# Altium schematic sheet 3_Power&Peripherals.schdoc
size 309 x 223 mm; Symbol: Artery_A4; Device: Artery_A4; Company: Artery Technology; Drawed: SD; Version: 1.1; Page Size: A4; @Project Name: p_AT-START-F437; @Page Count: 5; @Update Date: 2023-04-14 17:11:57; @Create Date: 2022-12-01; @Schematic Name: AT-START-F437 V1.1; @Page No: 3; @Page Name: Power&Peripherals
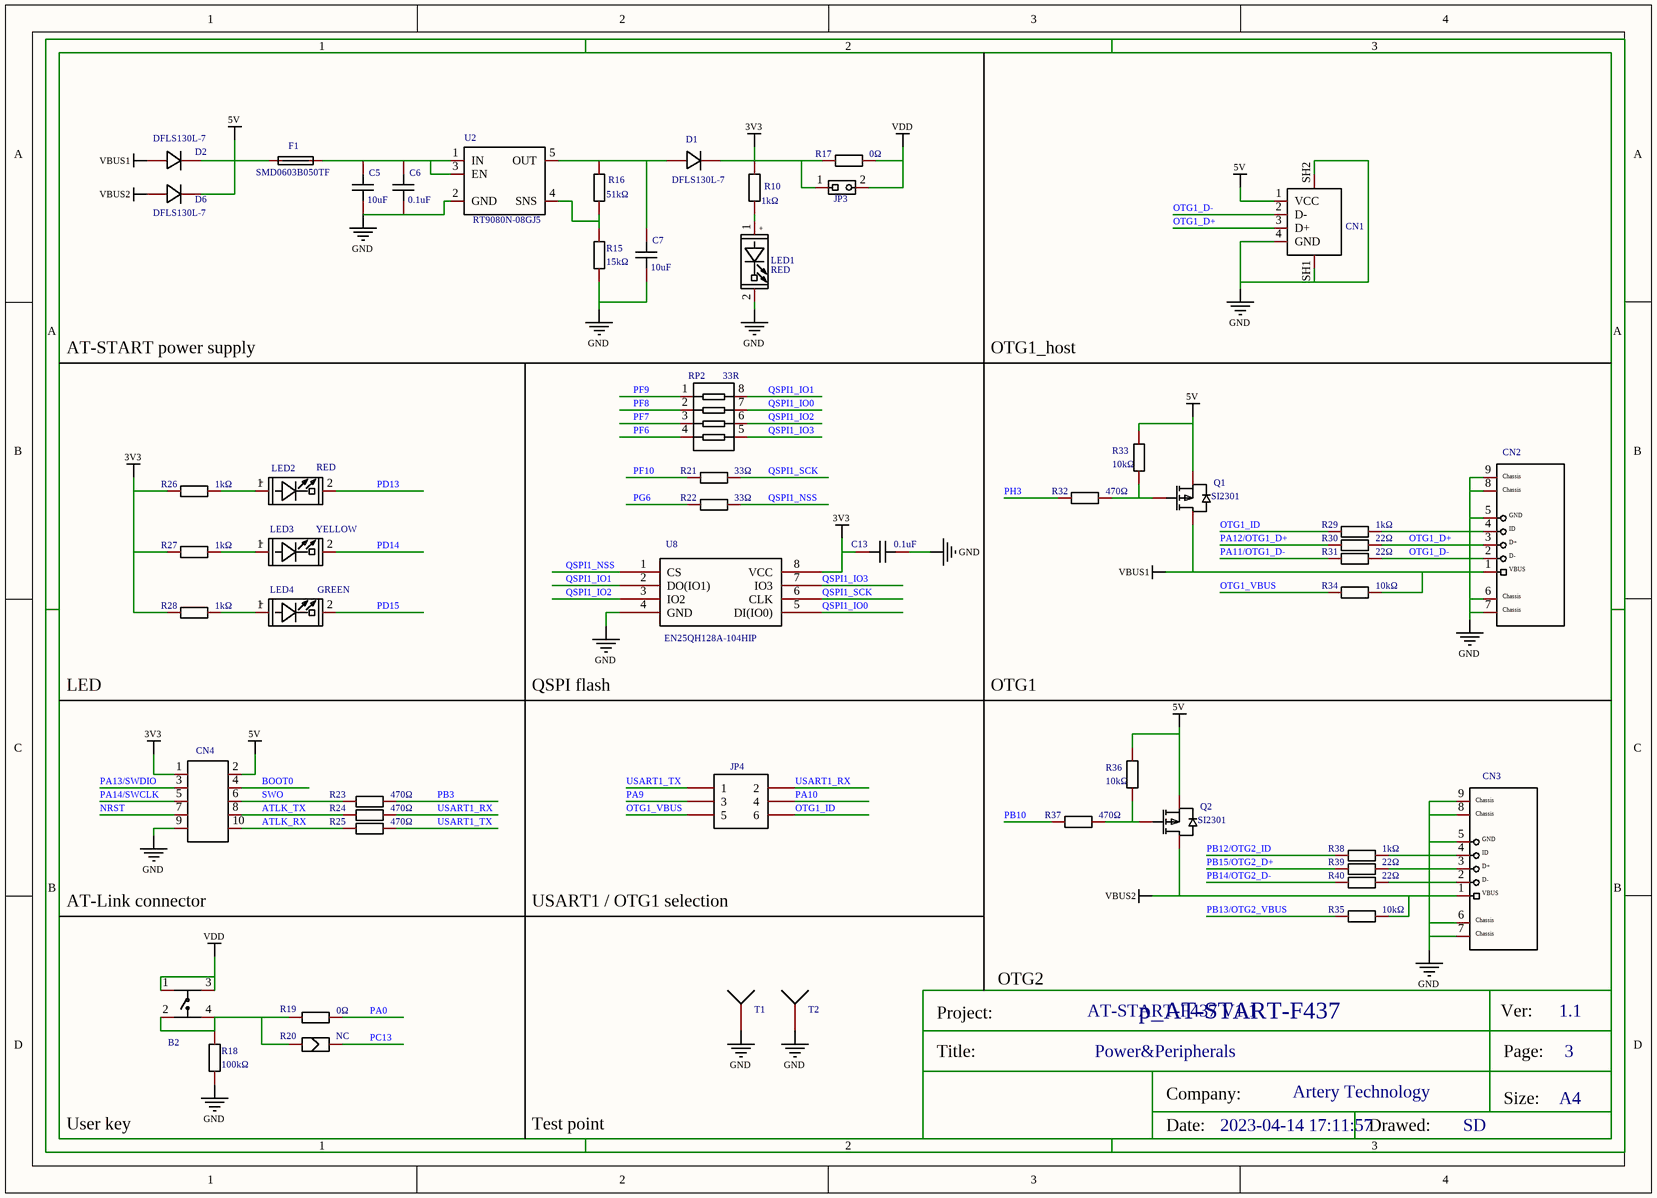
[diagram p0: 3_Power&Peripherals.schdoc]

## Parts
B2  贴片按键6*6*5 红色  [SW-SMD_4P-L6.0-W6.0-P4.50-LS9.0]  (value not drawn)
C5  10uF  [0603_C-M]
C6  0.1uF  [0603_C-M]
C7  10uF  [0603_C-M]
C13  0.1uF  [0603_C-M]
CN1  JTJ-USB-AF-08  [USB-A-TH__USB-AF-90]  (value not drawn)
CN2  USB_micro B  [USB_MIC_DIP]  (value not drawn)
CN3  USB_micro B  [USB_MIC_DIP]  (value not drawn)
CN4  CON10A_0  [HDR2X5]  (value not drawn)
D1  DFLS130L-7  [POWERDI-123_L2.8-W1.8-LS3.7-RD]
D2  DFLS130L-7  [POWERDI-123_L2.8-W1.8-LS3.7-RD]
D6  DFLS130L-7  [POWERDI-123_L2.8-W1.8-LS3.7-RD]
F1  SMD0603B050TF  [R0603]
JP3  Jumper 1x2P  [HEADER 1X2]  (value not drawn)
JP4  Header 3X2  [HDR2X3]  (value not drawn)
LED1  RED  [LED0603]
LED2  RED  [LED0603]
LED3  YELLOW  [LED0603]
LED4  GREEN  [LED0603]
Q1  SI2301  [SOT-23-3_L2.9-W1.3-P1.90-LS2.4-BR]
Q2  SI2301  [SOT-23-3_L2.9-W1.3-P1.90-LS2.4-BR]
R10  1kΩ  [R0603]
R15  15kΩ  [R0603]
R16  51kΩ  [R0603]
R17  0Ω  [R0603]
R18  100kΩ  [R0603]
R19  0Ω  [R0603]
R20  NC  [SB-PAD]
R21  33Ω  [R0603]
R22  33Ω  [R0603]
R23  470Ω  [R0603]
R24  470Ω  [R0603]
R25  470Ω  [R0603]
R26  1kΩ  [R0603]
R27  1kΩ  [R0603]
R28  1kΩ  [R0603]
R29  1kΩ  [R0603]
R30  22Ω  [R0603]
R31  22Ω  [R0603]
R32  470Ω  [R0603]
R33  10kΩ  [R0603]
R34  10kΩ  [R0603]
R35  10kΩ  [R0603]
R36  10kΩ  [R0603]
R37  470Ω  [R0603]
R38  1kΩ  [R0603]
R39  22Ω  [R0603]
R40  22Ω  [R0603]
RP2  33R  [0603*4,8P4R]
T1  TESTPOINT TP-5006  [TESTHOOK]  (value not drawn)
T2  TESTPOINT TP-5006  [TESTHOOK]  (value not drawn)
U2  RT9080N-08GJ5  [SOT-23-5]
U8  EN25QH128A-104HIP  [SOIC-8_208MIL]

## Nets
3V3: C13.1 CN4.1 D1.1 JP3.1 R10.1 R17.1 R26.1 R27.1 R28.1 U8.8(VCC)
5V: CN1.1(VCC) CN4.2 D2.1 D6.1 F1.1 Q1.2(S) Q2.2(S) R33.2 R36.2
GND: C5.2 C6.2 C7.2 C13.2 CN1.4(GND) CN1.SH1 CN1.SH2 CN2.5(GND) CN2.6 CN2.7 CN2.8 CN2.9 CN3.5(GND) CN3.6 CN3.7 CN3.8 CN3.9 CN4.9 LED1.2(CATHODE) R15.2 R18.1 T1.1 T2.1 U2.2(GND) U8.4(GND)
VBUS1: CN2.1(VBUS) D2.2 Q1.3(D) R34.2
VBUS2: CN3.1(VBUS) D6.2 Q2.3(D) R35.2
VDD: B2.1 B2.3 JP3.2 R17.2
ATLK_RX: CN4.10 R25.1
ATLK_TX: CN4.8 R24.1
BOOT0: CN4.4
NRST: CN4.7
OTG1_D+: CN1.3(D+) CN2.3(D+) R30.2
OTG1_D-: CN1.2(D-) CN2.2(D-) R31.2
OTG1_ID: JP4.6 R29.1
OTG1_VBUS: JP4.5 R34.1
PA0: R19.2
PA9: JP4.3
PA10: JP4.4
PA11/OTG1_D-: R31.1
PA12/OTG1_D+: R30.1
PA13/SWDIO: CN4.3
PA14/SWCLK: CN4.5
PB3: R23.2
PB10: R37.1
PB12/OTG2_ID: R38.1
PB13/OTG2_VBUS: R35.1
PB14/OTG2_D-: R40.1
PB15/OTG2_D+: R39.1
PC13: R20.2
PD13: LED2.2(CATHODE)
PD14: LED3.2(CATHODE)
PD15: LED4.2(CATHODE)
PF6: RP2.4
PF7: RP2.3
PF8: RP2.2
PF9: RP2.1
PF10: R21.1
PG6: R22.1
PH3: R32.1
QSPI1_IO0: RP2.7 U8.5(DI(IO0))
QSPI1_IO1: RP2.8 U8.2(DO(IO1))
QSPI1_IO2: RP2.6 U8.3(IO2)
QSPI1_IO3: RP2.5 U8.7(IO3)
QSPI1_NSS: R22.2 U8.1(CS)
QSPI1_SCK: R21.2 U8.6(CLK)
SWO: CN4.6 R23.1
USART1_RX: JP4.2 R24.2
USART1_TX: JP4.1 R25.2
NetB2_2: B2.2 B2.4 R18.2 R19.1 R20.1
NetC5_1: C5.1 C6.1 F1.2 U2.1(IN) U2.3(EN)
NetC7_1: C7.1 D1.2 R16.2 U2.5(OUT)
NetCN2_4: CN2.4(ID) R29.2
NetCN3_2: CN3.2(D-) R40.2
NetCN3_3: CN3.3(D+) R39.2
NetCN3_4: CN3.4(ID) R38.2
NetLED1_1: LED1.1(ANODE) R10.2
NetLED2_1: LED2.1(ANODE) R26.2
NetLED3_1: LED3.1(ANODE) R27.2
NetLED4_1: LED4.1(ANODE) R28.2
NetQ1_1: Q1.1(G) R32.2 R33.1
NetQ2_1: Q2.1(G) R36.1 R37.2
NetR15_1: R15.1 R16.1 U2.4(SNS)

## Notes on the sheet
- AT-START power supply
- OTG1_host
- LED
- QSPI flash
- OTG1
- AT-Link connector
- USART1 / OTG1 selection
- OTG2
- User key
- Test point

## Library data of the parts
B2 = K2-1102SP-C3SC-04: Manufacturer: Korean Hroparts Elec; Symbol: 贴片按键6*6*5 黑色; Paste Type: expand; Convert to PCB: yes
C5 C7 = 10uF: Convert to PCB: yes
C6 C13 = 0.1uF: Convert to PCB: yes
CN1 = JTJ-USB-AF-08: Paste Type: expand; Convert to PCB: yes
CN2 CN3 = USB_micro B: Convert to PCB: yes
CN4 = CON10A_0: Convert to PCB: yes
D1 D2 D6 = DFLS130L-7: Manufacturer: Diodes Incorporated; Paste Type: expand; Convert to PCB: yes
F1 = SMD0603B035TF: Manufacturer: Brightking Elec (TAIWAN); Paste Type: expand; Convert to PCB: yes
JP3 = Jumper 1x2P: Convert to PCB: yes
JP4 = Header 3X2: Convert to PCB: yes
LED1 LED2 = RED: Convert to PCB: yes
LED3 = YELLOW: Convert to PCB: yes
LED4 = GREEN: Convert to PCB: yes
Q1 Q2 = 2301: Manufacturer: FM; Paste Type: recommend; Convert to PCB: yes
R10 R26-R29 R38 = 0603WAF1001T5E: 电阻类型:厚膜电阻;阻值:1kΩ;精度:±1%;功率:100mW;温度系数:±100ppm/℃;最大工作电压:75V;工作温度范围:-55℃~+155℃;; Manufacturer: UNI-ROYAL(厚声); Add into BOM: yes; Tolerance: ±1%; Power(Watts): 100mW; Overload Voltage (Max): 75V
R15 = 0603WAF1502T5E: 电阻类型:厚膜电阻;阻值:15kΩ;精度:±1%;功率:100mW;温度系数:±100ppm/℃;最大工作电压:75V;工作温度范围:-55℃~+155℃;; Manufacturer: UNI-ROYAL(厚声); Add into BOM: yes; Tolerance: ±1%; Power(Watts): 100mW; Overload Voltage (Max): 75V
R16 = 0603WAF5102T5E: 电阻类型:厚膜电阻;阻值:51kΩ;精度:±1%;功率:100mW;温度系数:±100ppm/℃;最大工作电压:75V;工作温度范围:-55℃~+155℃;; Manufacturer: UNI-ROYAL(厚声); Add into BOM: yes; Tolerance: ±1%; Power(Watts): 100mW; Overload Voltage (Max): 75V
R17 R19 = 0603WAF0000T5E: 电阻类型:厚膜电阻;阻值:0Ω;精度:±1%;功率:100mW;最大工作电压:75V;工作温度范围:-55℃~+155℃;; Manufacturer: UNI-ROYAL(厚声); Add into BOM: yes; Tolerance: ±1%; Power(Watts): 100mW; Overload Voltage (Max): 75V
R18 = 0603WAF1003T5E: 电阻类型:厚膜电阻;阻值:100kΩ;精度:±1%;功率:100mW;温度系数:±100ppm/℃;最大工作电压:75V;工作温度范围:-55℃~+155℃;; Manufacturer: UNI-ROYAL(厚声); Add into BOM: yes; Tolerance: ±1%; Power(Watts): 100mW; Overload Voltage (Max): 75V
R20 = NC: Convert to PCB: yes
R21 R22 = 0603WAF330JT5E: 电阻类型:厚膜电阻;阻值:33Ω;精度:±1%;功率:100mW;温度系数:±100ppm/℃;最大工作电压:75V;工作温度范围:-55℃~+155℃;; Manufacturer: UNI-ROYAL(厚声); Add into BOM: yes; Tolerance: ±1%; Power(Watts): 100mW; Overload Voltage (Max): 75V
R23-R25 R32 R37 = 0603WAF4700T5E: 电阻类型:厚膜电阻;阻值:470Ω;精度:±1%;功率:100mW;温度系数:±100ppm/℃;最大工作电压:75V;工作温度范围:-55℃~+155℃;; Manufacturer: UNI-ROYAL(厚声); Add into BOM: yes; Tolerance: ±1%; Power(Watts): 100mW; Overload Voltage (Max): 75V
R30 R31 R39 R40 = 0603WAF220JT5E: 电阻类型:厚膜电阻;阻值:22Ω;精度:±1%;功率:100mW;温度系数:±100ppm/℃;最大工作电压:75V;工作温度范围:-55℃~+155℃;; Manufacturer: UNI-ROYAL(厚声); Add into BOM: yes; Tolerance: ±1%; Power(Watts): 100mW; Overload Voltage (Max): 75V
R33-R36 = 0603WAF1002T5E: 电阻类型:厚膜电阻;阻值:10kΩ;精度:±1%;功率:100mW;温度系数:±100ppm/℃;最大工作电压:75V;工作温度范围:-55℃~+155℃;; Manufacturer: UNI-ROYAL(厚声); Add into BOM: yes; Tolerance: ±1%; Power(Watts): 100mW; Overload Voltage (Max): 75V
RP2 = 33R: Convert to PCB: yes
T1 T2 = TESTPOINT TP-5006: Convert to PCB: yes
U2 = RT9080N-08GJ5: Convert to PCB: yes
U8 = EN25QH128A-104HIP: Convert to PCB: yes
